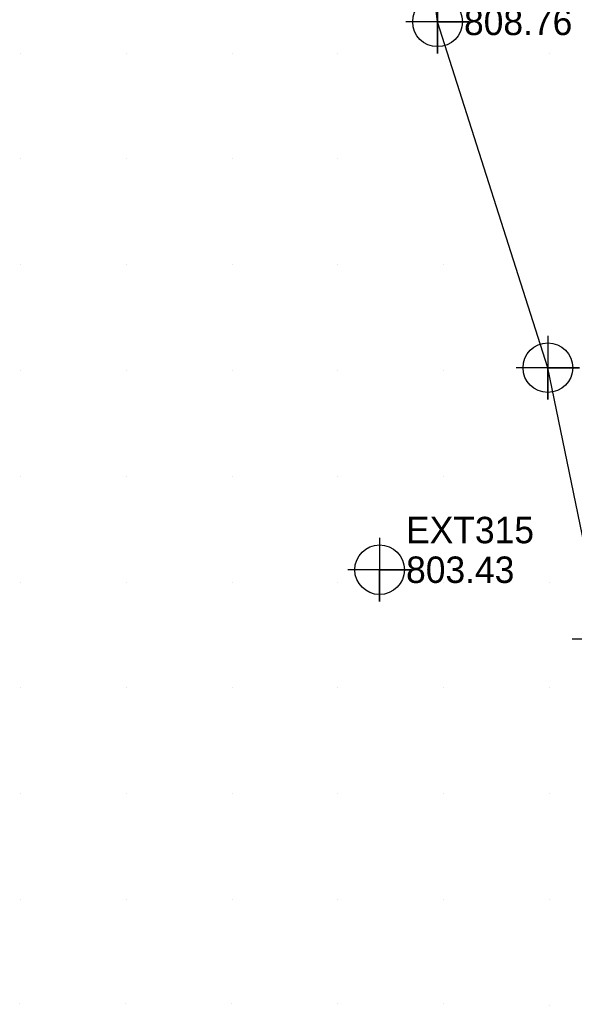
# Model space of a CAD drawing. Extents: x 1762120 to 1766775, y 709485 to 712965.
# Drawn here: x 1763750 to 1763802.3, y 712560 to 712653.2 of the extents above; entities that cross this region are included whole.
import ezdxf

# ---------------------------------------------------------------- set-up
doc = ezdxf.new("R2010")
doc.units = 0
for name, color, linetype in [('Exist DTM Breakline', 7, 'Continuous'), ('Exist DTM Breakline Cogo Elevation', 7, 'Continuous'), ('Exist DTM Breakline Cogo Point CELL', 7, 'Continuous'), ('Exist DTM QL2 LIDAR Elevation Point', 7, 'Continuous'), ('Exist DTM Regular Point CELL', 7, 'Continuous'), ('Exist DTM Regular Point Cogo Elevation', 7, 'Continuous'), ('Exist DTM Regular Point Cogo Number', 7, 'Continuous')]:
    doc.layers.add(name, color=color, linetype=linetype)

msp = doc.modelspace()

# ---------------------------------------------------------------- linework, layer by layer
at = {"layer": 'Exist DTM Breakline'}
msp.add_lwpolyline([(1763816.336, 712568.975), (1763813.77, 712594.344), (1763809.401, 712612.263), (1763805.117, 712594.603), (1763799.817, 712620.266), (1763789.401, 712652.954), (1763785.334, 712685.719)], dxfattribs=at)
at = {"layer": 'Exist DTM Breakline Cogo Point CELL'}
for points in [[(1763789.401, 712655.954), (1763789.401, 712649.954), (1763789.401, 712652.954), (1763792.401, 712652.954), (1763786.401, 712652.954)], [(1763799.817, 712623.266), (1763799.817, 712617.266), (1763799.817, 712620.266), (1763802.817, 712620.266), (1763796.817, 712620.266)], [(1763805.117, 712597.603), (1763805.117, 712591.603), (1763805.117, 712594.603), (1763808.117, 712594.603), (1763802.117, 712594.603)]]:
    msp.add_lwpolyline(points, dxfattribs=at)
for centre in [(1763789.401, 712652.954), (1763799.817, 712620.266)]:
    msp.add_circle(centre, 2.344, dxfattribs=at)
at = {"layer": 'Exist DTM QL2 LIDAR Elevation Point'}
for p, q in [((1763750, 712650), (1763750, 712650)), ((1763760, 712650), (1763760, 712650)), ((1763770, 712650), (1763770, 712650)), ((1763780, 712650), (1763780, 712650)), ((1763800, 712650), (1763800, 712650)), ((1763750, 712640), (1763750, 712640)), ((1763760, 712640), (1763760, 712640)), ((1763770, 712640), (1763770, 712640)), ((1763780, 712640), (1763780, 712640)), ((1763750, 712630), (1763750, 712630)), ((1763760, 712630), (1763760, 712630)), ((1763770, 712630), (1763770, 712630)), ((1763780, 712630), (1763780, 712630)), ((1763790, 712630), (1763790, 712630)), ((1763750, 712620), (1763750, 712620)), ((1763760, 712620), (1763760, 712620)), ((1763770, 712620), (1763770, 712620)), ((1763780, 712620), (1763780, 712620)), ((1763790, 712620), (1763790, 712620)), ((1763750, 712610), (1763750, 712610)), ((1763760, 712610), (1763760, 712610)), ((1763770, 712610), (1763770, 712610)), ((1763780, 712610), (1763780, 712610)), ((1763790, 712610), (1763790, 712610)), ((1763750, 712600), (1763750, 712600)), ((1763760, 712600), (1763760, 712600)), ((1763770, 712600), (1763770, 712600)), ((1763780, 712600), (1763780, 712600)), ((1763790, 712600), (1763790, 712600)), ((1763800, 712600), (1763800, 712600)), ((1763750, 712590), (1763750, 712590)), ((1763760, 712590), (1763760, 712590)), ((1763770, 712590), (1763770, 712590)), ((1763780, 712590), (1763780, 712590)), ((1763790, 712590), (1763790, 712590)), ((1763800, 712590), (1763800, 712590)), ((1763750, 712580), (1763750, 712580)), ((1763760, 712580), (1763760, 712580)), ((1763770, 712580), (1763770, 712580)), ((1763780, 712580), (1763780, 712580)), ((1763790, 712580), (1763790, 712580)), ((1763800, 712580), (1763800, 712580)), ((1763750, 712570), (1763750, 712570)), ((1763760, 712570), (1763760, 712570)), ((1763770, 712570), (1763770, 712570)), ((1763780, 712570), (1763780, 712570)), ((1763790, 712570), (1763790, 712570)), ((1763800, 712570), (1763800, 712570)), ((1763749.951, 712560.164), (1763749.951, 712560.164)), ((1763759.952, 712560.164), (1763759.952, 712560.164)), ((1763769.954, 712560.164), (1763769.954, 712560.164)), ((1763779.955, 712560.164), (1763779.955, 712560.164)), ((1763789.956, 712560.164), (1763789.956, 712560.164)), ((1763800, 712560), (1763800, 712560))]:
    msp.add_line(p, q, dxfattribs=at)
at = {"layer": 'Exist DTM Regular Point CELL'}
msp.add_lwpolyline([(1763783.931, 712604.169), (1763783.931, 712598.169), (1763783.931, 712601.169), (1763786.931, 712601.169), (1763780.931, 712601.169)], dxfattribs=at)
msp.add_circle((1763783.931, 712601.169), 2.344, dxfattribs=at)

# ---------------------------------------------------------------- texts
at = {"layer": 'Exist DTM Breakline Cogo Elevation'}
msp.add_text('808.76', height=2.5, dxfattribs=at).set_placement((1763791.901, 712651.704))
at = {"layer": 'Exist DTM Regular Point Cogo Elevation'}
msp.add_text('803.43', height=2.5, dxfattribs=at).set_placement((1763786.431, 712599.919))
at = {"layer": 'Exist DTM Regular Point Cogo Number'}
msp.add_text('EXT315', height=2.5, dxfattribs=at).set_placement((1763786.431, 712603.669))

doc.saveas('drawing.dxf')
